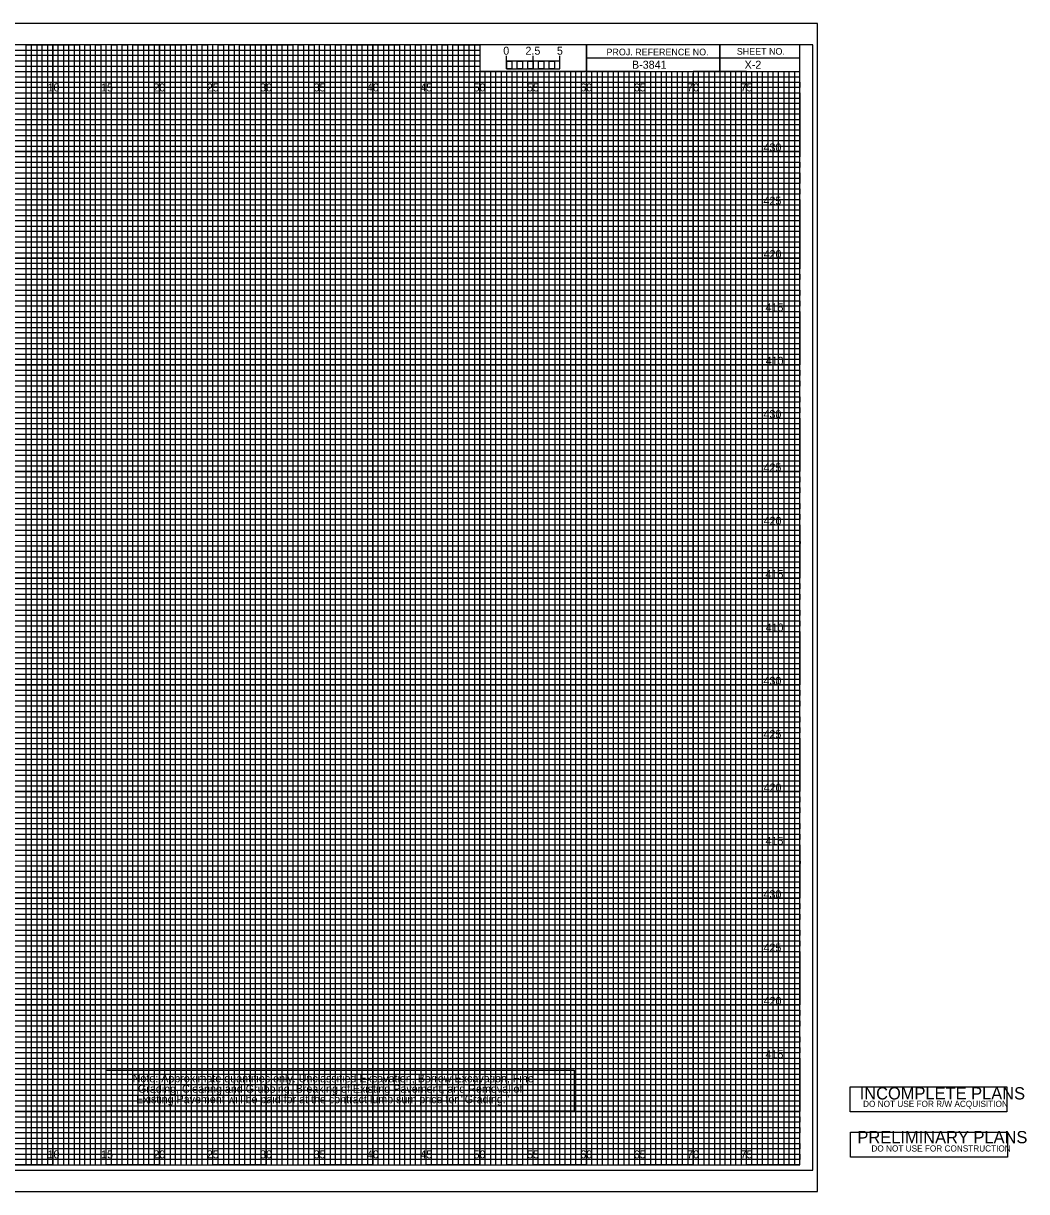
# Model space of a CAD drawing. Extents: x -7 to 181, y -2 to 107.
# Drawn here: x 87.2 to 181.2, y -2.5 to 107 of the extents above; entities that cross this region are included whole.
import ezdxf

# ---------------------------------------------------------------- set-up
doc = ezdxf.new("R2010")
doc.units = 0
for name, color, linetype in [('Prop Grid Mask', 7, 'Continuous'), ('Prop XS Bar Scale Labels', 7, 'Continuous'), ('Prop XS Elevation Labels', 7, 'Continuous'), ('Prop XS Offset Labels', 7, 'Continuous'), ('Prop XS Project Number', 7, 'Continuous'), ('Prop XS Sheet Number', 7, 'Continuous'), ('Prop XSC Text', 7, 'Continuous'), ('Sheet Cross Section CELL', 7, 'Continuous'), ('Sheet Cross Section Grid Major CELL', 7, 'Continuous'), ('Sheet Cross Section Grid Middle CELL', 7, 'Continuous'), ('Sheet Cross Section Grid Minor 1 CELL', 7, 'Continuous'), ('Sheet Cross Section Grid Minor 2 CELL', 7, 'Continuous'), ('Sheet Cross Section Scale CELL', 7, 'Continuous'), ('Sheet Cutting Line CELL', 7, 'Continuous'), ('Sheet DOT Grid CELL', 7, 'Continuous'), ('Sheet Plot Border Inside CELL', 7, 'Continuous'), ('Sheet Plot Border Outside CELL', 7, 'Continuous'), ('Sheet Sticker Incomplete CELL', 7, 'Continuous'), ('Sheet Sticker Preliminary CELL', 7, 'Continuous')]:
    doc.layers.add(name, color=color, linetype=linetype)

msp = doc.modelspace()

# ---------------------------------------------------------------- linework, layer by layer
at = {"layer": 'Prop Grid Mask'}
msp.add_lwpolyline([(95, 8.87), (138.84, 8.87), (138.84, 5.03), (95, 5.03)], close=True, dxfattribs=at)
at = {"layer": 'Sheet Cross Section CELL'}
for p, q in [((152.5, 105), (152.5, 102.5)), ((152.5, 102.5), (152.5, 105)), ((160, 103.75), (140, 103.75)), ((140, 103.75), (140, 102.5)), ((140, 102.5), (160, 102.5))]:
    msp.add_line(p, q, dxfattribs=at)
for points in [[(160, 105), (0, 105), (0, 0), (160, 0)], [(140, 105), (130, 105), (130, 102.52), (140, 102.52)], [(160, 105), (140, 105), (140, 102.5), (160, 102.5)]]:
    msp.add_lwpolyline(points, close=True, dxfattribs=at)
at = {"layer": 'Sheet Cross Section Grid Major CELL'}
for p, q in [((95, 105), (90, 105)), ((90, 105), (90, 0)), ((95, 0), (95, 105)), ((105, 105), (100, 105)), ((100, 105), (100, 0)), ((105, 0), (105, 105)), ((115, 105), (110, 105)), ((110, 105), (110, 0)), ((115, 0), (115, 105)), ((125, 105), (120, 105)), ((120, 105), (120, 0)), ((125, 0), (125, 105)), ((130, 105), (130, 0)), ((135, 0), (135, 102.5)), ((145, 102.5), (140, 102.5)), ((140, 102.5), (140, 0)), ((145, 0), (145, 102.5)), ((155, 102.5), (150, 102.5)), ((150, 102.5), (150, 0)), ((155, 0), (155, 102.5)), ((90, 0), (85, 0)), ((100, 0), (95, 0)), ((110, 0), (105, 0)), ((120, 0), (115, 0)), ((130, 0), (125, 0)), ((140, 0), (135, 0)), ((150, 0), (145, 0)), ((160, 0), (155, 0)), ((160, 0), (160, 0))]:
    msp.add_line(p, q, dxfattribs=at)
for points in [[(0, 100), (160, 100), (160, 95), (0, 95)], [(0, 90), (160, 90), (160, 85), (0, 85)], [(0, 80), (160, 80), (160, 75), (0, 75)], [(0, 70), (160, 70), (160, 65), (0, 65)], [(0, 60), (160, 60), (160, 55), (0, 55)], [(0, 50), (160, 50), (160, 45), (0, 45)], [(0, 40), (160, 40), (160, 35), (0, 35)], [(0, 30), (160, 30), (160, 25), (0, 25)], [(0, 20), (160, 20), (160, 15), (0, 15)], [(0, 10), (160, 10), (160, 5), (0, 5)]]:
    msp.add_lwpolyline(points, dxfattribs=at)
at = {"layer": 'Sheet Cross Section Grid Middle CELL'}
for points in [[(82.5, 0), (87.5, 0), (87.5, 105), (92.5, 105), (92.5, 0), (97.5, 0), (97.5, 105), (102.5, 105), (102.5, 0), (107.5, 0), (107.5, 105), (112.5, 105), (112.5, 0), (117.5, 0), (117.5, 105), (122.5, 105), (122.5, 0), (127.5, 0), (127.5, 105), (129.97, 105), (130, 105), (130, 102.5), (132.5, 102.5), (132.5, 0), (137.5, 0), (137.5, 102.5), (142.5, 102.5), (142.5, 0), (147.5, 0), (147.5, 102.5), (152.5, 102.5), (152.5, 0), (157.5, 0), (157.5, 102.5)], [(0, 102.5), (137.5, 102.5)], [(0, 92.5), (160, 92.5), (160, 97.5), (0, 97.5)], [(0, 82.5), (160, 82.5), (160, 87.5), (0, 87.5)], [(0, 72.5), (160, 72.5), (160, 77.5), (0, 77.5)], [(0, 62.5), (160, 62.5), (160, 67.5), (0, 67.5)], [(0, 52.5), (160, 52.5), (160, 57.5), (0, 57.5)], [(0, 42.5), (160, 42.5), (160, 47.5), (0, 47.5)], [(0, 32.5), (160, 32.5), (160, 37.5), (0, 37.5)], [(0, 22.5), (160, 22.5), (160, 27.5), (0, 27.5)], [(0, 12.5), (160, 12.5), (160, 17.5), (0, 17.5)], [(0, 2.5), (160, 2.5), (160, 7.5), (0, 7.5)]]:
    msp.add_lwpolyline(points, dxfattribs=at)
at = {"layer": 'Sheet Cross Section Grid Minor 1 CELL'}
for p, q in [((0, 104.5), (130, 104.5)), ((130, 104.5), (130, 103.99)), ((130, 103.99), (0, 103.99)), ((0, 103.5), (130, 103.5)), ((130, 102.95), (0, 102.95)), ((130, 103.5), (130, 102.95)), ((0, 102), (160, 102))]:
    msp.add_line(p, q, dxfattribs=at)
for points in [[(0, 101.5), (135, 101.5), (160, 101.5), (160, 101), (0, 101)], [(0, 100.5), (160, 100.5), (160, 99.5), (0, 99.5)], [(0, 99), (160, 99), (160, 98.5), (0, 98.49)], [(0, 98), (160, 98), (160, 97), (0, 97)], [(0, 96.5), (160, 96.5), (160, 96), (0, 96)], [(0, 95.5), (160, 95.5), (160, 94.5), (0, 94.5)], [(0, 94), (160, 94), (160, 93.5), (0, 93.5)], [(0, 93), (160, 93), (160, 92), (0, 92)], [(0, 91.5), (160, 91.5), (160, 91), (0, 91)], [(0, 90.5), (160, 90.5), (160, 89.5), (0, 89.5)], [(0, 89), (160, 89), (160, 88.5), (0, 88.5)], [(0, 88), (160, 88), (160, 86.98), (160, 86.5), (160, 86), (0, 86)], [(0, 87), (160, 87), (160, 86.5), (0, 86.5)], [(0, 85.5), (160, 85.5), (160, 84.5), (0, 84.52)], [(0, 84.52), (160, 84.5), (160, 84), (0, 84)], [(0, 83.5), (160, 83.5), (160, 83), (0, 83)], [(0, 82), (160, 82), (160, 81.5), (0, 81.5)], [(0, 81), (160, 81), (160, 80.5), (0, 80.5)], [(-0.04, 79.45), (160, 79.45), (160, 78.94), (-0.04, 78.94)], [(0, 78.5), (160, 78.5), (160, 78), (0, 78)], [(0, 77), (160, 77), (160, 76.5), (0, 76.5)], [(0, 76), (160, 76), (160, 75.5), (0, 75.5)], [(0, 74.5), (160, 74.5), (160, 74), (0, 74)], [(0, 73.5), (160, 73.5), (160, 73), (0, 73)], [(0, 72), (160, 72), (160, 71.5), (0, 71.5)], [(0, 71), (160, 71), (160, 70.5), (0, 70.5)], [(0, 69.5), (160, 69.5), (160, 68.99), (0, 69)], [(0, 68.5), (160, 68.5), (160, 68), (0, 68)], [(0, 67), (160, 67), (160, 66.5), (0, 66.5)], [(0, 66), (160, 66), (160, 65.5), (0, 65.5)], [(0, 64.5), (160, 64.5), (160, 64), (0, 64)], [(0, 63.5), (160, 63.5), (160, 63), (0, 63)], [(0, 62), (160, 62), (160, 61.5), (0, 61.5)], [(0, 61), (160, 61), (160, 60.5), (0, 60.5)], [(0, 59.5), (160, 59.5), (160, 59), (0, 59)], [(0, 58.5), (160.03, 58.45), (160, 58), (0, 58)], [(0, 57), (160, 57), (160, 56.5), (0, 56.5)], [(0, 56), (160, 56), (160, 55.5), (0, 55.5)], [(0, 54.5), (160, 54.5), (160, 54), (0, 54)], [(0, 53.5), (160, 53.5), (160, 53), (0, 53)], [(0, 52), (160, 52), (160, 51.5), (0, 51.5)], [(0, 51), (160, 51), (160, 50.5), (0, 50.5)], [(0, 49.5), (160, 49.5), (160, 49), (0, 49)], [(0, 48.5), (160, 48.5), (160, 48), (0, 48)], [(0, 47), (160, 47), (160, 46.5), (0, 46.5)], [(0, 46), (160, 46), (160, 45.5), (0, 45.5)], [(0, 44.5), (160, 44.5), (160, 44), (0, 44)], [(0, 43.5), (160, 43.5), (160, 43), (0, 43)], [(0, 42), (160, 42), (160, 41.5), (0, 41.5)], [(0, 41), (160, 41), (160, 40.5), (0, 40.5)], [(0, 39.5), (160, 39.5), (160, 38.99), (0, 39)], [(0, 38.5), (160, 38.5), (160, 38), (0, 38)], [(0, 37), (160, 37), (160, 36.5), (0, 36.5)], [(0, 36), (160, 36), (160, 35.5), (0, 35.5)], [(0, 34.5), (160, 34.5), (160, 34), (0, 34)], [(0, 33.5), (160, 33.5), (160, 33), (0, 33)], [(0, 32), (160, 32), (160, 31.5), (0, 31.5)], [(0, 31), (160, 31), (160, 30.5), (0, 30.5)], [(0, 29.5), (160, 29.5), (160, 29), (0, 29)], [(0, 28.5), (160.03, 28.46), (160, 28), (0, 28)], [(0, 27), (160, 27), (160, 26.5), (0, 26.5)], [(0, 26), (160, 26), (160, 25.5), (0, 25.5)], [(0, 24.5), (160, 24.5), (160, 24), (0, 24)], [(0, 23.5), (160, 23.5), (160, 23), (0, 23)], [(0, 22), (160, 22), (160, 21.5), (0, 21.5)], [(0, 21), (160, 21), (160, 20.5), (0, 20.5)], [(0, 19.5), (160, 19.5), (160, 19), (0, 19)], [(0, 18.5), (160, 18.5), (160, 18), (0, 18)], [(0, 17), (160, 17), (160, 16.5), (0, 16.5)], [(0, 16), (160, 16), (160, 15.5), (0, 15.5)], [(0, 14.5), (160, 14.5), (160, 14), (0, 14)], [(0, 13.5), (160, 13.5), (160, 13), (0, 13)], [(0, 12), (160, 12), (160, 11.5), (0, 11.5)], [(0, 11), (160, 11), (160, 10.5), (0, 10.5)], [(0, 9.5), (160, 9.5), (160, 9), (0, 9)], [(0, 8.5), (160, 8.5), (160, 8), (0, 8)], [(0, 7), (160, 7), (160, 6.5), (0, 6.5)], [(0, 6), (160, 6), (160, 5.5), (0, 5.5)], [(0, 4.5), (160, 4.5), (160, 4), (0, 4)], [(0, 3.5), (160, 3.5), (160, 3), (0, 3)], [(0, 2), (160, 2), (160, 1.5), (0, 1.5)], [(0, 1), (160, 1), (160, 0.5), (0, 0.5)]]:
    msp.add_lwpolyline(points, dxfattribs=at)
at = {"layer": 'Sheet Cross Section Grid Minor 2 CELL'}
for p, q in [((133.5, 102.5), (133, 102.5)), ((133, 102.5), (133, 0)), ((133.5, 0), (133.5, 102.5)), ((134.5, 102.5), (134, 102.5)), ((134, 102.5), (134, 0)), ((134.5, 0), (134.5, 102.5)), ((133, 0), (132.5, 0)), ((134, 0), (133.5, 0))]:
    msp.add_line(p, q, dxfattribs=at)
for points in [[(87.5, 0), (88, 0), (88, 105), (88.5, 105), (88.5, 0)], [(88.5, 0), (89, 0), (89, 105), (89.5, 105), (89.5, 0)], [(90, 0), (90.5, 0), (90.5, 105), (91, 105), (91, 0)], [(91, 0), (91.5, 0), (91.5, 105), (92, 105), (92, 0)], [(92.5, 0), (93, 0), (93, 105), (93.5, 105), (93.5, 0)], [(93.5, 0), (94, 0), (94, 105), (94.5, 105), (94.5, 0)], [(95, 0), (95.5, 0), (95.5, 105), (96, 105), (96, 0)], [(96, 0), (96.5, 0), (96.5, 105), (97, 105), (97, 0)], [(97.5, 0), (98, 0), (98, 105), (98.5, 105), (98.5, 0)], [(98.5, 0), (99, 0), (99, 105), (99.5, 105), (99.5, 0)], [(100, 0), (100.5, 0), (100.5, 105), (101, 105), (101, 0)], [(101, 0), (101.5, 0), (101.5, 105), (102, 105), (102, 0)], [(102.5, 0), (103, 0), (103, 105), (103.5, 105), (103.5, 0)], [(103.5, 0), (104, 0), (104, 105), (104.5, 105), (104.5, 0)], [(105, 0), (105.5, 0), (105.5, 105), (106, 105), (106, 0)], [(106, 0), (106.5, 0), (106.5, 105), (107, 105), (107, 0)], [(107.5, 0), (108, 0), (108, 105), (108.5, 105), (108.5, 0)], [(108.5, 0), (109, 0), (109, 105), (109.5, 105), (109.5, 0)], [(110, 0), (110.5, 0), (110.5, 105), (111, 105), (111, 0)], [(111, 0), (111.5, 0), (111.5, 105), (112, 105), (112, 0)], [(112.5, 0), (113, 0), (113, 105), (113.5, 105), (113.5, 0)], [(113.5, 0), (114, 0), (114, 105), (114.5, 105), (114.5, 0)], [(115, 0), (115.5, 0), (115.5, 105), (116, 105), (116, 0)], [(116, 0), (116.5, 0), (116.5, 105), (117, 105), (117, 0)], [(117.5, 0), (118, 0), (118, 105), (118.5, 105), (118.5, 0)], [(118.5, 0), (119, 0), (119, 105), (119.5, 105), (119.5, 0)], [(120, 0), (120.5, 0), (120.5, 105), (121, 105), (121, 0)], [(121, 0), (121.5, 0), (121.5, 105), (122, 105), (122, 0)], [(122.5, 0), (123, 0), (123, 105), (123.5, 105), (123.5, 0)], [(123.5, 0), (124, 0), (124, 105), (124.5, 105), (124.5, 0)], [(125, 0), (125.5, 0), (125.5, 105), (126, 105), (126, 0)], [(126, 0), (126.5, 0), (126.5, 105), (127, 105), (127, 0)], [(127.5, 0), (128, 0), (128, 105), (128.5, 105), (128.5, 0)], [(128.5, 0), (129, 0), (129, 105), (129.5, 105), (129.5, 0)], [(130, 0), (130.5, 0), (130.5, 102.5), (131.01, 102.5), (131.01, 0)], [(131, 0), (131.5, 0), (131.5, 102.5), (132, 102.5), (132, 0)], [(135, 0), (135.49, 0), (135.49, 102.5), (136, 102.5), (136, 0)], [(136, 0), (136.5, 0), (136.5, 102.5), (137.03, 102.5), (137.03, 0)], [(137.5, 0), (138, 0), (138, 102.5), (138.5, 102.5), (138.5, 0)], [(138.5, 0), (139, 0), (139, 102.5), (139.5, 102.5), (139.5, 0)], [(140, 0), (140.5, 0), (140.5, 102.5), (141, 102.5), (141, 0)], [(141, 0), (141.5, 0), (141.5, 102.5), (142, 102.5), (142, 0)], [(142.5, 0), (143, 0), (143, 102.5), (143.5, 102.5), (143.5, 0)], [(143.5, 0), (144, 0), (144, 102.5), (144.5, 102.5), (144.5, 0)], [(145, 0), (145.5, 0), (145.5, 102.5), (146, 102.5), (146, 0)], [(146, 0), (146.5, 0), (146.5, 102.5), (147, 102.5), (147, 0)], [(147.5, 0), (148, 0), (148, 102.5), (148.5, 102.5), (148.5, 0)], [(148.5, 0), (149, 0), (149, 102.5), (149.5, 102.5), (149.5, 0)], [(150, 0), (150.5, 0), (150.5, 102.5), (151, 102.5), (151, 0)], [(151, 0), (151.5, 0), (151.5, 102.5), (152, 102.5), (152, 0)], [(152.5, 0), (153, 0), (153, 102.5), (153.5, 102.5), (153.5, 0)], [(153.5, 0), (154, 0), (154, 102.5), (154.5, 102.5), (154.5, 0)], [(155, 0), (155.5, 0), (155.5, 102.5), (156, 102.5), (156, 0)], [(156, 0), (156.5, 0), (156.5, 102.5), (157, 102.5), (157, 0)], [(157.5, 0), (158, 0), (158, 102.5), (158.5, 102.5), (158.5, 0)], [(158.5, 0), (159, 0), (159, 102.5), (159.5, 102.5), (159.5, 0)]]:
    msp.add_lwpolyline(points, dxfattribs=at)
at = {"layer": 'Sheet Cross Section Scale CELL'}
for p, q in [((132.5, 102.75), (132.5, 103.95)), ((132.5, 103.45), (132.5, 103.95)), ((135, 102.75), (135, 103.95)), ((137.5, 102.75), (137.5, 103.95)), ((137.5, 103.45), (137.5, 103.95))]:
    msp.add_line(p, q, dxfattribs=at)
for points in [[(137.5, 103.45), (132.5, 103.45), (132.5, 102.75), (137.5, 102.75)], [(132.5, 103.45), (133, 103.45), (133, 102.75), (132.5, 102.75)], [(133.5, 103.45), (134, 103.45), (134, 102.75), (133.5, 102.75)], [(134.5, 103.45), (135, 103.45), (135, 102.75), (134.5, 102.75)], [(135.5, 103.45), (136, 103.45), (136, 102.75), (135.5, 102.75)], [(136.5, 103.45), (137, 103.45), (137, 102.75), (136.5, 102.75)]]:
    msp.add_lwpolyline(points, close=True, dxfattribs=at)
at = {"layer": 'Sheet Cutting Line CELL'}
for p, q in [((161.65, 107), (-6.7, 107)), ((-6.7, -2.5), (161.65, -2.5))]:
    msp.add_line(p, q, dxfattribs=at)
at = {"layer": 'Sheet DOT Grid CELL'}
for p, q in [((90, 0), (90, 105)), ((95, 0), (95, 105)), ((100, 0), (100, 105)), ((105, 0), (105, 105)), ((110, 0), (110, 105)), ((115, 0), (115, 105)), ((120, 0), (120, 105)), ((125, 0), (125, 105)), ((130, 0), (130, 102.34)), ((135, 0), (135, 102.34)), ((140, 0), (140, 102.34)), ((145, 0), (145, 102.34)), ((150, 0), (150, 102.34)), ((155, 0), (155, 102.34)), ((0, 100), (160, 100)), ((0, 95), (160, 95)), ((0, 90), (160, 90)), ((0, 85), (160, 85)), ((0, 80), (160, 80)), ((0, 75), (160, 75)), ((0, 70), (160, 70)), ((0, 65), (160, 65)), ((0, 60), (160, 60)), ((0, 55), (160, 55)), ((0, 50), (160, 50)), ((0, 45), (160, 45)), ((0, 40), (160, 40)), ((0, 35), (160, 35)), ((0, 30), (160, 30)), ((0, 25), (160, 25)), ((0, 20), (160, 20)), ((0, 15), (160, 15)), ((0, 10), (160, 10)), ((0, 5), (160, 5))]:
    msp.add_line(p, q, dxfattribs=at)
at = {"layer": 'Sheet Plot Border Inside CELL'}
msp.add_lwpolyline([(-5.4, -0.5), (161.2, -0.5), (161.2, 105), (-5.4, 105)], close=True, dxfattribs=at)
at = {"layer": 'Sheet Plot Border Outside CELL'}
msp.add_lwpolyline([(-6.7, -2.5), (161.65, -2.5), (161.65, 107), (-6.7, 107)], close=True, dxfattribs=at)
at = {"layer": 'Sheet Sticker Incomplete CELL'}
msp.add_lwpolyline([(164.7, 4.97), (164.7, 7.32), (179.4, 7.32), (179.4, 4.97)], close=True, dxfattribs=at)
at = {"layer": 'Sheet Sticker Preliminary CELL'}
msp.add_lwpolyline([(164.74, 0.72), (164.74, 3.07), (179.44, 3.07), (179.44, 0.72)], close=True, dxfattribs=at)

# ---------------------------------------------------------------- texts
at = {"layer": 'Prop XS Bar Scale Labels'}
for s, p in [('2.5', (134.29, 104.06)), ('5', (137.24, 104.06))]:
    msp.add_text(s, height=0.75, dxfattribs=at).set_placement(p)
at = {"layer": 'Prop XS Elevation Labels'}
for s, p in [('430', (156.59, 95)), ('425', (156.59, 90)), ('420', (156.6, 85)), ('415', (156.78, 80)), ('410', (156.79, 75)), ('430', (156.59, 70)), ('425', (156.59, 65)), ('420', (156.6, 60)), ('415', (156.78, 55)), ('410', (156.79, 50)), ('430', (156.59, 45)), ('425', (156.59, 40)), ('420', (156.6, 35)), ('415', (156.78, 30)), ('430', (156.59, 25)), ('425', (156.59, 20)), ('420', (156.6, 15)), ('415', (156.78, 10))]:
    msp.add_text(s, height=0.75, dxfattribs=at).set_placement(p)
at = {"layer": 'Prop XS Offset Labels'}
for s, p in [('10', (89.52, 100.62)), ('15', (94.53, 100.62)), ('20', (99.43, 100.62)), ('25', (104.44, 100.62)), ('30', (109.43, 100.62)), ('35', (114.44, 100.62)), ('40', (119.43, 100.62)), ('45', (124.44, 100.62)), ('50', (129.43, 100.62)), ('55', (134.44, 100.62)), ('60', (139.43, 100.62)), ('65', (144.44, 100.62)), ('70', (149.43, 100.62)), ('75', (154.44, 100.62)), ('10', (89.52, 0.62)), ('15', (94.53, 0.62)), ('20', (99.43, 0.62)), ('25', (104.44, 0.62)), ('30', (109.43, 0.62)), ('35', (114.44, 0.62)), ('40', (119.43, 0.62)), ('45', (124.44, 0.62)), ('50', (129.43, 0.62)), ('55', (134.44, 0.62)), ('60', (139.43, 0.62)), ('65', (144.44, 0.62)), ('70', (149.43, 0.62)), ('75', (154.44, 0.62))]:
    msp.add_text(s, height=0.75, dxfattribs=at).set_placement(p)
at = {"layer": 'Prop XS Project Number'}
msp.add_text('B-3841', height=0.75, dxfattribs=at).set_placement((144.27, 102.75))
at = {"layer": 'Prop XS Sheet Number'}
msp.add_text('X-2', height=0.75, dxfattribs=at).set_placement((154.82, 102.75))
at = {"layer": 'Prop XSC Text'}
for s, p in [('Note: Approximate quantities only. Unclassified Excavation, Borrow Excavation, Fine ', (97.49, 7.75)), (' Existing Pavement will be paid for at the contract lump sum price for "Grading."', (97.53, 5.79)), ('Grading, Clearing and Grubbing, Breaking of Existing Pavement, and Removal of', (97.99, 6.77))]:
    msp.add_text(s, height=0.75, dxfattribs=at).set_placement(p)
at = {"layer": 'Sheet Cross Section CELL'}
for s, p in [('PROJ. REFERENCE NO.', (141.88, 104)), ('SHEET NO.', (154.09, 104.06))]:
    msp.add_text(s, height=0.625, dxfattribs=at).set_placement(p)
at = {"layer": 'Sheet Cross Section Scale CELL'}
msp.add_text('0', height=0.75, dxfattribs=at).set_placement((132.21, 104.06))
at = {"layer": 'Sheet Sticker Incomplete CELL'}
for s, height, p in [('INCOMPLETE PLANS', 1.152, (165.6, 6.14)), ('DO NOT USE FOR R/W ACQUISITION', 0.576, (165.92, 5.44))]:
    msp.add_text(s, height=height, dxfattribs=at).set_placement(p)
at = {"layer": 'Sheet Sticker Preliminary CELL'}
for s, height, p in [('PRELIMINARY PLANS', 1.152, (165.39, 2.03)), ('DO NOT USE FOR CONSTRUCTION', 0.576, (166.7, 1.26))]:
    msp.add_text(s, height=height, dxfattribs=at).set_placement(p)

doc.saveas('drawing.dxf')
